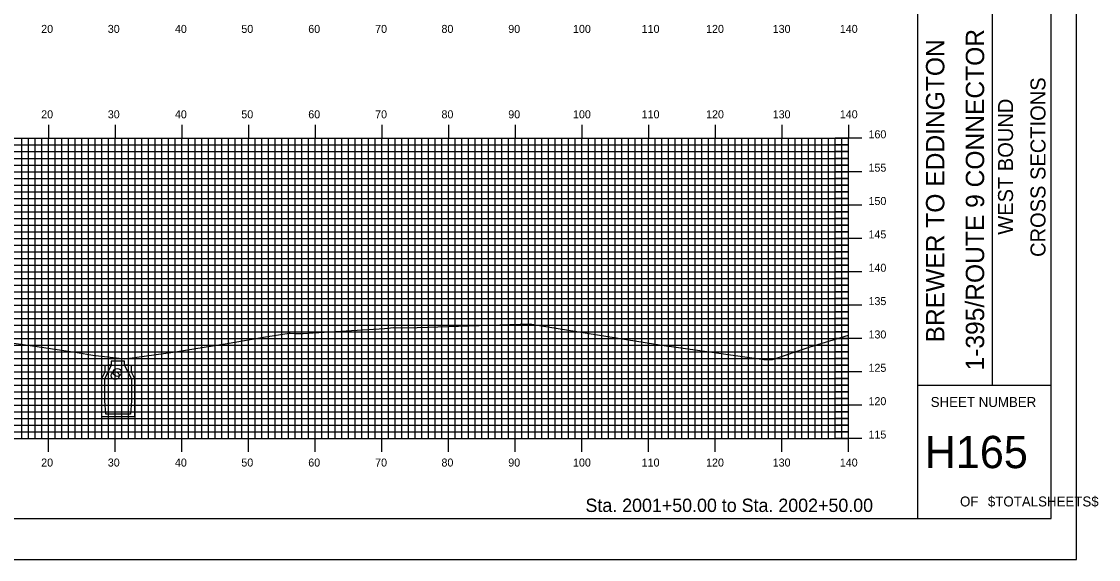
# Model space of a CAD drawing. Extents: x 851139 to 851482, y 366605 to 366825.
# Drawn here: x 851320.9 to 851482.4, y 366604.9 to 366685.6 of the extents above; entities that cross this region are included whole.
import ezdxf

# ---------------------------------------------------------------- set-up
doc = ezdxf.new("R2010")
doc.units = 0
for name, color, linetype in [('BORDER', 7, 'Continuous'), ('H_V ANNOTATION', 7, 'Continuous'), ('M_Roadway_Centerline', 7, 'Continuous'), ('MAJOR', 7, 'Continuous'), ('MINOR', 7, 'Continuous'), ('PLOT BOUNDARY', 7, 'Continuous'), ('S_Drainage_CB', 7, 'Continuous'), ('S_Drainage_Invert', 7, 'Continuous'), ('S_Roadway_Centerline', 7, 'Continuous')]:
    doc.layers.add(name, color=color, linetype=linetype)

msp = doc.modelspace()

# ---------------------------------------------------------------- linework, layer by layer
at = {"layer": 'BORDER'}
for p, q in [((851455.34, 366611.06), (851455.34, 366821.06)), ((851466.52, 366631.06), (851466.52, 366701.06)), ((851455.34, 366631.06), (851475.34, 366631.06))]:
    msp.add_line(p, q, dxfattribs=at)
msp.add_lwpolyline([(851155.34, 366611.06), (851475.34, 366611.06), (851475.34, 366821.06), (851155.34, 366821.06)], close=True, dxfattribs=at)
at = {"layer": 'MAJOR'}
for p, q in [((851324.94, 366670.06), (851324.94, 366668.06)), ((851334.94, 366670.06), (851334.94, 366668.06)), ((851344.94, 366670.06), (851344.94, 366668.06)), ((851354.94, 366670.06), (851354.94, 366668.06)), ((851364.94, 366670.06), (851364.94, 366668.06)), ((851374.94, 366670.06), (851374.94, 366668.06)), ((851384.94, 366670.06), (851384.94, 366668.06)), ((851394.94, 366670.06), (851394.94, 366668.06)), ((851404.94, 366670.06), (851404.94, 366668.06)), ((851414.94, 366670.06), (851414.94, 366668.06)), ((851424.94, 366670.06), (851424.94, 366668.06)), ((851434.94, 366670.06), (851434.94, 366668.06)), ((851444.94, 366670.06), (851444.94, 366668.06)), ((851164.94, 366668.06), (851444.94, 366668.06)), ((851164.94, 366668.06), (851444.94, 366668.06)), ((851324.94, 366623.06), (851324.94, 366668.06)), ((851334.94, 366623.06), (851334.94, 366668.06)), ((851344.94, 366623.06), (851344.94, 366668.06)), ((851354.94, 366623.06), (851354.94, 366668.06)), ((851364.94, 366623.06), (851364.94, 366668.06)), ((851374.94, 366623.06), (851374.94, 366668.06)), ((851384.94, 366623.06), (851384.94, 366668.06)), ((851394.94, 366623.06), (851394.94, 366668.06)), ((851404.94, 366623.06), (851404.94, 366668.06)), ((851414.94, 366623.06), (851414.94, 366668.06)), ((851424.94, 366623.06), (851424.94, 366668.06)), ((851434.94, 366623.06), (851434.94, 366668.06)), ((851446.94, 366668.06), (851442.93, 366668.06)), ((851444.94, 366623.06), (851444.94, 366668.06)), ((851444.94, 366623.06), (851444.94, 366668.06)), ((851164.94, 366663.06), (851444.94, 366663.06)), ((851446.94, 366663.06), (851442.93, 366663.06)), ((851164.94, 366658.06), (851444.94, 366658.06)), ((851446.94, 366658.06), (851442.93, 366658.06)), ((851164.94, 366653.06), (851444.94, 366653.06)), ((851446.94, 366653.06), (851442.93, 366653.06)), ((851164.94, 366648.06), (851444.94, 366648.06)), ((851446.94, 366648.06), (851442.93, 366648.06)), ((851164.94, 366643.06), (851444.94, 366643.06)), ((851446.94, 366643.06), (851442.93, 366643.06)), ((851164.94, 366638.06), (851444.94, 366638.06)), ((851446.94, 366638.06), (851442.93, 366638.06)), ((851164.94, 366633.06), (851444.94, 366633.06)), ((851446.94, 366633.06), (851442.93, 366633.06)), ((851164.94, 366628.06), (851444.94, 366628.06)), ((851446.94, 366628.06), (851442.93, 366628.06)), ((851164.94, 366623.06), (851444.94, 366623.06)), ((851164.94, 366623.06), (851444.94, 366623.06)), ((851324.94, 366621.05), (851324.94, 366623.06)), ((851334.94, 366621.05), (851334.94, 366623.06)), ((851344.94, 366621.05), (851344.94, 366623.06)), ((851354.94, 366621.05), (851354.94, 366623.06)), ((851364.94, 366621.05), (851364.94, 366623.06)), ((851374.94, 366621.05), (851374.94, 366623.06)), ((851384.94, 366621.05), (851384.94, 366623.06)), ((851394.94, 366621.05), (851394.94, 366623.06)), ((851404.94, 366621.05), (851404.94, 366623.06)), ((851414.94, 366621.05), (851414.94, 366623.06)), ((851424.94, 366621.05), (851424.94, 366623.06)), ((851434.94, 366621.05), (851434.94, 366623.06)), ((851446.94, 366623.06), (851442.93, 366623.06)), ((851444.94, 366621.05), (851444.94, 366623.06))]:
    msp.add_line(p, q, dxfattribs=at)
at = {"layer": 'MINOR'}
for p, q in [((851320.94, 366623.06), (851320.94, 366668.06)), ((851321.94, 366623.06), (851321.94, 366668.06)), ((851322.94, 366623.06), (851322.94, 366668.06)), ((851323.94, 366623.06), (851323.94, 366668.06)), ((851325.94, 366623.06), (851325.94, 366668.06)), ((851326.94, 366623.06), (851326.94, 366668.06)), ((851327.94, 366623.06), (851327.94, 366668.06)), ((851328.94, 366623.06), (851328.94, 366668.06)), ((851329.94, 366623.06), (851329.94, 366668.06)), ((851330.94, 366623.06), (851330.94, 366668.06)), ((851331.94, 366623.06), (851331.94, 366668.06)), ((851332.94, 366623.06), (851332.94, 366668.06)), ((851333.94, 366623.06), (851333.94, 366668.06)), ((851335.94, 366623.06), (851335.94, 366668.06)), ((851336.94, 366623.06), (851336.94, 366668.06)), ((851337.94, 366623.06), (851337.94, 366668.06)), ((851338.94, 366623.06), (851338.94, 366668.06)), ((851339.94, 366623.06), (851339.94, 366668.06)), ((851340.94, 366623.06), (851340.94, 366668.06)), ((851341.94, 366623.06), (851341.94, 366668.06)), ((851342.94, 366623.06), (851342.94, 366668.06)), ((851343.94, 366623.06), (851343.94, 366668.06)), ((851345.94, 366623.06), (851345.94, 366668.06)), ((851346.94, 366623.06), (851346.94, 366668.06)), ((851347.94, 366623.06), (851347.94, 366668.06)), ((851348.94, 366623.06), (851348.94, 366668.06)), ((851349.94, 366623.06), (851349.94, 366668.06)), ((851350.94, 366623.06), (851350.94, 366668.06)), ((851351.94, 366623.06), (851351.94, 366668.06)), ((851352.94, 366623.06), (851352.94, 366668.06)), ((851353.94, 366623.06), (851353.94, 366668.06)), ((851355.94, 366623.06), (851355.94, 366668.06)), ((851356.94, 366623.06), (851356.94, 366668.06)), ((851357.94, 366623.06), (851357.94, 366668.06)), ((851358.94, 366623.06), (851358.94, 366668.06)), ((851359.94, 366623.06), (851359.94, 366668.06)), ((851360.94, 366623.06), (851360.94, 366668.06)), ((851361.94, 366623.06), (851361.94, 366668.06)), ((851362.94, 366623.06), (851362.94, 366668.06)), ((851363.94, 366623.06), (851363.94, 366668.06)), ((851365.94, 366623.06), (851365.94, 366668.06)), ((851366.94, 366623.06), (851366.94, 366668.06)), ((851367.94, 366623.06), (851367.94, 366668.06)), ((851368.94, 366623.06), (851368.94, 366668.06)), ((851369.94, 366623.06), (851369.94, 366668.06)), ((851370.94, 366623.06), (851370.94, 366668.06)), ((851371.94, 366623.06), (851371.94, 366668.06)), ((851372.94, 366623.06), (851372.94, 366668.06)), ((851373.94, 366623.06), (851373.94, 366668.06)), ((851375.94, 366623.06), (851375.94, 366668.06)), ((851376.94, 366623.06), (851376.94, 366668.06)), ((851377.94, 366623.06), (851377.94, 366668.06)), ((851378.94, 366623.06), (851378.94, 366668.06)), ((851379.94, 366623.06), (851379.94, 366668.06)), ((851380.94, 366623.06), (851380.94, 366668.06)), ((851381.94, 366623.06), (851381.94, 366668.06)), ((851382.94, 366623.06), (851382.94, 366668.06)), ((851383.94, 366623.06), (851383.94, 366668.06)), ((851385.94, 366623.06), (851385.94, 366668.06)), ((851386.94, 366623.06), (851386.94, 366668.06)), ((851387.94, 366623.06), (851387.94, 366668.06)), ((851388.94, 366623.06), (851388.94, 366668.06)), ((851389.94, 366623.06), (851389.94, 366668.06)), ((851390.94, 366623.06), (851390.94, 366668.06)), ((851391.94, 366623.06), (851391.94, 366668.06)), ((851392.94, 366623.06), (851392.94, 366668.06)), ((851393.94, 366623.06), (851393.94, 366668.06)), ((851395.94, 366623.06), (851395.94, 366668.06)), ((851396.94, 366623.06), (851396.94, 366668.06)), ((851397.94, 366623.06), (851397.94, 366668.06)), ((851398.94, 366623.06), (851398.94, 366668.06)), ((851399.94, 366623.06), (851399.94, 366668.06)), ((851400.94, 366623.06), (851400.94, 366668.06)), ((851401.94, 366623.06), (851401.94, 366668.06)), ((851402.94, 366623.06), (851402.94, 366668.06)), ((851403.94, 366623.06), (851403.94, 366668.06)), ((851405.94, 366623.06), (851405.94, 366668.06)), ((851406.94, 366623.06), (851406.94, 366668.06)), ((851407.94, 366623.06), (851407.94, 366668.06)), ((851408.94, 366623.06), (851408.94, 366668.06)), ((851409.94, 366623.06), (851409.94, 366668.06)), ((851410.94, 366623.06), (851410.94, 366668.06)), ((851411.94, 366623.06), (851411.94, 366668.06)), ((851412.94, 366623.06), (851412.94, 366668.06)), ((851413.94, 366623.06), (851413.94, 366668.06)), ((851415.94, 366623.06), (851415.94, 366668.06)), ((851416.94, 366623.06), (851416.94, 366668.06)), ((851417.94, 366623.06), (851417.94, 366668.06)), ((851418.94, 366623.06), (851418.94, 366668.06)), ((851419.94, 366623.06), (851419.94, 366668.06)), ((851420.94, 366623.06), (851420.94, 366668.06)), ((851421.94, 366623.06), (851421.94, 366668.06)), ((851422.94, 366623.06), (851422.94, 366668.06)), ((851423.94, 366623.06), (851423.94, 366668.06)), ((851425.94, 366623.06), (851425.94, 366668.06)), ((851426.94, 366623.06), (851426.94, 366668.06)), ((851427.94, 366623.06), (851427.94, 366668.06)), ((851428.94, 366623.06), (851428.94, 366668.06)), ((851429.94, 366623.06), (851429.94, 366668.06)), ((851430.94, 366623.06), (851430.94, 366668.06)), ((851431.94, 366623.06), (851431.94, 366668.06)), ((851432.94, 366623.06), (851432.94, 366668.06)), ((851433.94, 366623.06), (851433.94, 366668.06)), ((851435.94, 366623.06), (851435.94, 366668.06)), ((851436.94, 366623.06), (851436.94, 366668.06)), ((851437.94, 366623.06), (851437.94, 366668.06)), ((851438.94, 366623.06), (851438.94, 366668.06)), ((851439.94, 366623.06), (851439.94, 366668.06)), ((851440.94, 366623.06), (851440.94, 366668.06)), ((851441.94, 366623.06), (851441.94, 366668.06)), ((851442.94, 366623.06), (851442.94, 366668.06)), ((851443.94, 366623.06), (851443.94, 366668.06)), ((851164.94, 366667.06), (851444.94, 366667.06)), ((851164.94, 366666.06), (851444.94, 366666.06)), ((851444.94, 366667.06), (851442.93, 366667.06)), ((851444.94, 366666.06), (851442.93, 366666.06)), ((851164.94, 366665.06), (851444.94, 366665.06)), ((851444.94, 366665.06), (851442.93, 366665.06)), ((851164.94, 366664.06), (851444.94, 366664.06)), ((851444.94, 366664.06), (851442.93, 366664.06)), ((851164.94, 366662.06), (851444.94, 366662.06)), ((851444.94, 366662.06), (851442.93, 366662.06)), ((851164.94, 366661.06), (851444.94, 366661.06)), ((851164.94, 366660.06), (851444.94, 366660.06)), ((851444.94, 366661.06), (851442.93, 366661.06)), ((851444.94, 366660.06), (851442.93, 366660.06)), ((851164.94, 366659.06), (851444.94, 366659.06)), ((851444.94, 366659.06), (851442.93, 366659.06)), ((851164.94, 366657.06), (851444.94, 366657.06)), ((851444.94, 366657.06), (851442.93, 366657.06)), ((851164.94, 366656.06), (851444.94, 366656.06)), ((851164.94, 366655.06), (851444.94, 366655.06)), ((851444.94, 366656.06), (851442.93, 366656.06)), ((851444.94, 366655.06), (851442.93, 366655.06)), ((851164.94, 366654.06), (851444.94, 366654.06)), ((851444.94, 366654.06), (851442.93, 366654.06)), ((851164.94, 366652.06), (851444.94, 366652.06)), ((851444.94, 366652.06), (851442.93, 366652.06)), ((851164.94, 366651.06), (851444.94, 366651.06)), ((851164.94, 366650.06), (851444.94, 366650.06)), ((851444.94, 366651.06), (851442.93, 366651.06)), ((851444.94, 366650.06), (851442.93, 366650.06)), ((851164.94, 366649.06), (851444.94, 366649.06)), ((851444.94, 366649.06), (851442.93, 366649.06)), ((851164.94, 366647.06), (851444.94, 366647.06)), ((851444.94, 366647.06), (851442.93, 366647.06)), ((851164.94, 366646.06), (851444.94, 366646.06)), ((851164.94, 366645.06), (851444.94, 366645.06)), ((851444.94, 366646.06), (851442.93, 366646.06)), ((851444.94, 366645.06), (851442.93, 366645.06)), ((851164.94, 366644.06), (851444.94, 366644.06)), ((851444.94, 366644.06), (851442.93, 366644.06)), ((851164.94, 366642.06), (851444.94, 366642.06)), ((851444.94, 366642.06), (851442.93, 366642.06)), ((851164.94, 366641.06), (851444.94, 366641.06)), ((851444.94, 366641.06), (851442.93, 366641.06)), ((851164.94, 366640.06), (851444.94, 366640.06)), ((851164.94, 366639.06), (851444.94, 366639.06)), ((851444.94, 366640.06), (851442.93, 366640.06)), ((851444.94, 366639.06), (851442.93, 366639.06)), ((851164.94, 366637.06), (851444.94, 366637.06)), ((851444.94, 366637.06), (851442.93, 366637.06)), ((851164.94, 366636.06), (851444.94, 366636.06)), ((851444.94, 366636.06), (851442.93, 366636.06)), ((851164.94, 366635.06), (851444.94, 366635.06)), ((851164.94, 366634.06), (851444.94, 366634.06)), ((851444.94, 366635.06), (851442.93, 366635.06)), ((851444.94, 366634.06), (851442.93, 366634.06)), ((851164.94, 366632.06), (851444.94, 366632.06)), ((851444.94, 366632.06), (851442.93, 366632.06)), ((851164.94, 366631.06), (851444.94, 366631.06)), ((851444.94, 366631.06), (851442.93, 366631.06)), ((851164.94, 366630.06), (851444.94, 366630.06)), ((851164.94, 366629.06), (851444.94, 366629.06)), ((851444.94, 366630.06), (851442.93, 366630.06)), ((851444.94, 366629.06), (851442.93, 366629.06)), ((851164.94, 366627.06), (851444.94, 366627.06)), ((851164.94, 366626.06), (851444.94, 366626.06)), ((851444.94, 366627.06), (851442.93, 366627.06)), ((851444.94, 366626.06), (851442.93, 366626.06)), ((851164.94, 366625.06), (851444.94, 366625.06)), ((851164.94, 366624.06), (851444.94, 366624.06)), ((851444.94, 366625.06), (851442.93, 366625.06)), ((851444.94, 366624.06), (851442.93, 366624.06))]:
    msp.add_line(p, q, dxfattribs=at)
at = {"layer": 'PLOT BOUNDARY'}
msp.add_lwpolyline([(851139.15, 366604.94), (851479.15, 366604.94), (851479.15, 366824.94), (851139.15, 366824.94)], close=True, dxfattribs=at)
at = {"layer": 'S_Drainage_CB'}
for p, q in [((851334.37, 366634.01), (851333.38, 366634.01)), ((851333.38, 366634.01), (851333.38, 366633.03)), ((851333.38, 366632.01), (851334.37, 366634.01)), ((851337.38, 366634.01), (851336.37, 366634.01)), ((851336.37, 366634.01), (851337.38, 366632.01)), ((851337.38, 366633.03), (851337.38, 366634.01)), ((851333.38, 366633.03), (851332.89, 366632.01)), ((851332.89, 366632.01), (851332.89, 366626.37)), ((851333.38, 366628.7), (851333.38, 366632.01)), ((851337.88, 366632.01), (851337.38, 366633.03)), ((851337.38, 366632.01), (851337.38, 366628.7)), ((851337.88, 366626.37), (851337.88, 366632.01)), ((851333.55, 366626.7), (851333.38, 366628.7)), ((851337.38, 366628.7), (851337.22, 366626.7)), ((851332.89, 366626.37), (851337.88, 366626.37)), ((851337.22, 366626.7), (851333.55, 366626.7))]:
    msp.add_line(p, q, dxfattribs=at)
msp.add_lwpolyline([(851336.86, 366634.06), (851336.37, 366634.06), (851336.37, 366634.68), (851334.37, 366634.68), (851334.37, 366634.06), (851333.87, 366634.06)], dxfattribs=at)
at = {"layer": 'S_Drainage_Invert'}
for centre in [(851334.96, 366632.5), (851335.27, 366632.96)]:
    msp.add_circle(centre, 0.6, dxfattribs=at)
at = {"layer": 'S_Roadway_Centerline'}
msp.add_lwpolyline([(851311.69, 366638.49), (851322.88, 366636.91), (851329.25, 366635.97), (851331.62, 366635.54), (851336.41, 366635.01), (851343.98, 366636.05), (851345.47, 366636.32), (851352.02, 366637.38), (851357.17, 366638.23), (851361.03, 366638.84), (851361.2, 366638.84), (851361.87, 366638.82), (851362.39, 366638.8), (851363.16, 366638.81), (851363.83, 366638.86), (851375.36, 366639.56), (851376.7, 366639.7), (851378.09, 366639.66), (851380.26, 366639.71), (851392.65, 366640.11), (851397.17, 366640.23), (851398.31, 366640.05), (851415.98, 366637.19), (851416.31, 366637.14), (851416.59, 366637.09), (851432.24, 366634.92), (851433.56, 366634.91), (851439.21, 366636.8), (851444.94, 366638.57)], dxfattribs=at)

# ---------------------------------------------------------------- texts
at = {"layer": 'BORDER'}
for s, height, p in [('1-395/ROUTE 9 CONNECTOR', 2.7557, (851465.29, 366633.26)), ('BREWER TO EDDINGTON', 2.7557, (851459.32, 366637.46)), ('CROSS SECTIONS', 2.25, (851474.49, 366650.28)), ('WEST BOUND', 2.25, (851469.62, 366653.61))]:
    msp.add_text(s, height=height, rotation=90, dxfattribs=at).set_placement(p)
for s, height, p in [('SHEET NUMBER', 1.4905, (851457.27, 366627.79)), ('H165', 4.839, (851456.37, 366618.62)), ('OF', 1.491, (851461.67, 366612.88)), ('$TOTALSHEETS$', 1.4905, (851465.85, 366612.88))]:
    msp.add_text(s, height=height, dxfattribs=at).set_placement(p)
at = {"layer": 'H_V ANNOTATION'}
for s, height, p in [('20', 1.2, (851323.85, 366683.86)), ('30', 1.2, (851333.84, 366683.86)), ('40', 1.2, (851343.91, 366683.86)), ('50', 1.2, (851353.87, 366683.86)), ('60', 1.2, (851363.91, 366683.86)), ('70', 1.2, (851373.94, 366683.86)), ('80', 1.2, (851383.89, 366683.86)), ('90', 1.2, (851393.91, 366683.86)), ('100', 1.2, (851403.62, 366683.86)), ('110', 1.2, (851413.92, 366683.86)), ('120', 1.2, (851423.58, 366683.86)), ('130', 1.2, (851433.57, 366683.86)), ('140', 1.2, (851443.64, 366683.86)), ('20', 1.2, (851323.85, 366671.06)), ('30', 1.2, (851333.84, 366671.06)), ('40', 1.2, (851343.91, 366671.06)), ('50', 1.2, (851353.87, 366671.06)), ('60', 1.2, (851363.91, 366671.06)), ('70', 1.2, (851373.94, 366671.06)), ('80', 1.2, (851383.89, 366671.06)), ('90', 1.2, (851393.91, 366671.06)), ('100', 1.2, (851403.62, 366671.06)), ('110', 1.2, (851413.92, 366671.06)), ('120', 1.2, (851423.58, 366671.06)), ('130', 1.2, (851433.57, 366671.06)), ('140', 1.2, (851443.64, 366671.06)), ('160', 1.2, (851447.94, 366668.06)), ('155', 1.2, (851447.94, 366663.06)), ('150', 1.2, (851447.94, 366658.06)), ('145', 1.2, (851447.94, 366653.06)), ('140', 1.2, (851447.94, 366648.06)), ('135', 1.2, (851447.94, 366643.06)), ('130', 1.2, (851447.94, 366638.06)), ('125', 1.2, (851447.94, 366633.06)), ('120', 1.2, (851447.94, 366628.06)), ('115', 1.2, (851447.94, 366623.06)), ('20', 1.2, (851323.85, 366618.86)), ('30', 1.2, (851333.84, 366618.86)), ('40', 1.2, (851343.91, 366618.86)), ('50', 1.2, (851353.87, 366618.86)), ('60', 1.2, (851363.91, 366618.86)), ('70', 1.2, (851373.94, 366618.86)), ('80', 1.2, (851383.89, 366618.86)), ('90', 1.2, (851393.91, 366618.86)), ('100', 1.2, (851403.62, 366618.86)), ('110', 1.2, (851413.92, 366618.86)), ('120', 1.2, (851423.58, 366618.86)), ('130', 1.2, (851433.57, 366618.86)), ('140', 1.2, (851443.64, 366618.86)), ('Sta. 2001+50.00 to Sta. 2002+50.00', 2.0004, (851405.49, 366612.05))]:
    msp.add_text(s, height=height, dxfattribs=at).set_placement(p)
at = {"layer": 'M_Roadway_Centerline'}
for s, p in [('C', (851376.7, 366639.7)), ('L', (851376.7, 366639.69))]:
    msp.add_text(s, height=0.0146, dxfattribs=at).set_placement(p)

doc.saveas('drawing.dxf')
